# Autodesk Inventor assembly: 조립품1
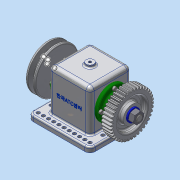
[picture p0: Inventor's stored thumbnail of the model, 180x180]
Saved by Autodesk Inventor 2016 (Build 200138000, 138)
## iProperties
Created: 2018-11
Part Number: 조립품1
Material: 일반
Document SubType Name: Assembly
Designer: PC-2
Author: PC-2
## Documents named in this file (12)
- C:\Users\PC-2\Desktop\481108V1020\OldVersions\조립품1.iam
- C:\Users\PC-2\Desktop\481108V1020\부품2.ipt
- C:\Users\PC-2\Desktop\481108V1020\베어링 6203.ipt
- C:\Users\PC-2\Desktop\481108V1020\축.ipt
- C:\Users\PC-2\Desktop\481108V1020\부시.ipt
- C:\Users\PC-2\Desktop\481108V1020\커버.ipt
- C:\Users\PC-2\Desktop\481108V1020\볼트 M4.ipt
- C:\Users\PC-2\Desktop\481108V1020\키 5x5x12.ipt
- C:\Users\PC-2\Desktop\481108V1020\V벨트풀리.ipt
- C:\Users\PC-2\Desktop\481108V1020\와셔 12x24.ipt
- C:\Users\PC-2\Desktop\481108V1020\너트 M12x1.25.ipt
- C:\Users\PC-2\Desktop\481108V1020\스퍼기어.ipt
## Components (1 placed, 1 different names)
1. V벨트풀리:1
